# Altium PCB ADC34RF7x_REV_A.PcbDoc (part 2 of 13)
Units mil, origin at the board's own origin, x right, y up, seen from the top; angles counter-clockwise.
Board outline 6250 x 2716.54 mil, 18 copper layers (Top Layer, L2 GND, L3 PWR, L4 GND, L5 PWR/SIG, L6 GND, L7 SIGNAL, L8 GND, L9 GND, L10 SIGNAL, L11 GND, L12 SIGNAL, L13 GND, L14 PWR, L15 GND, L16 PWR/SIG, L16 GND, Bottom Layer), stack 95.314 mil thick; 668 components, 786 nets, 3150 pads, 2020 vias.
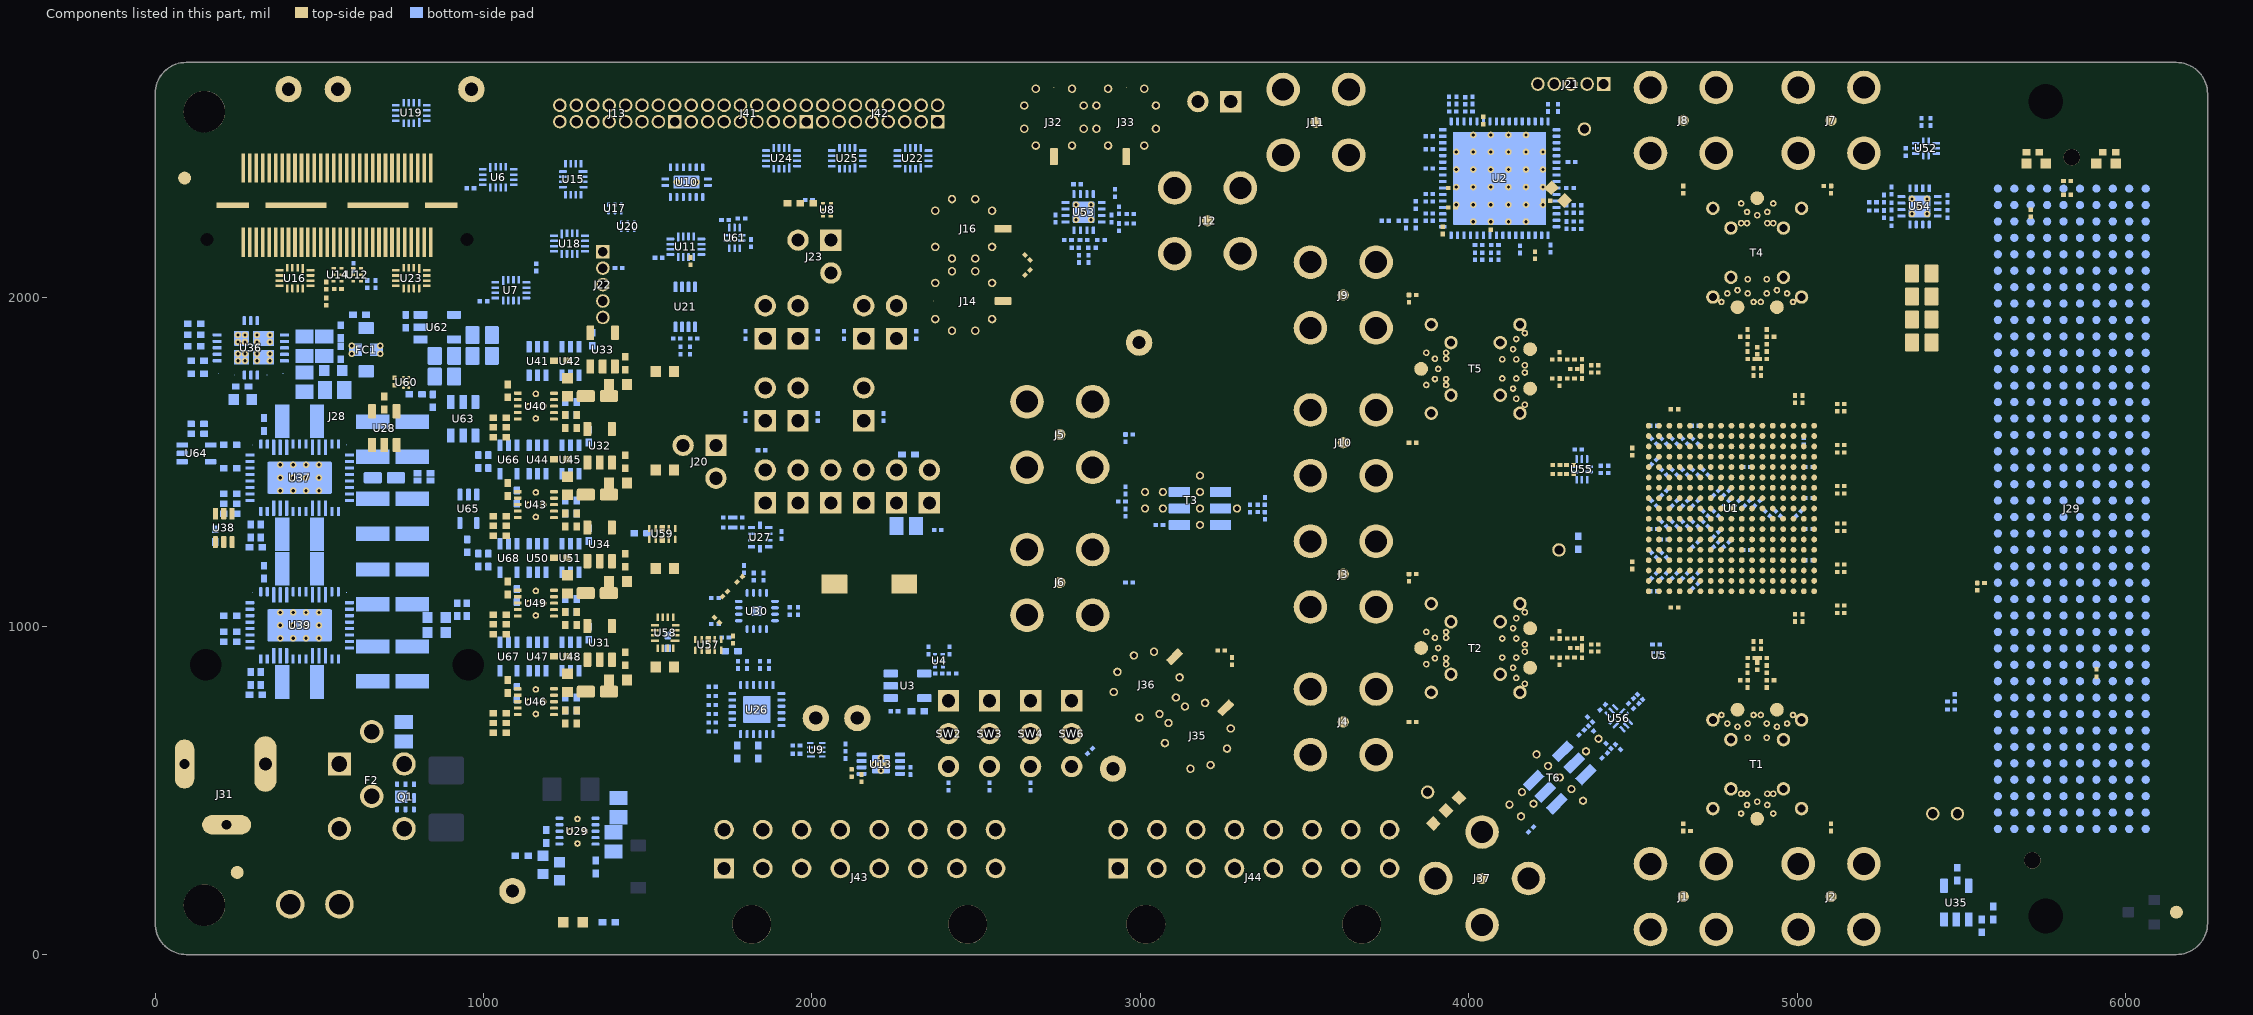
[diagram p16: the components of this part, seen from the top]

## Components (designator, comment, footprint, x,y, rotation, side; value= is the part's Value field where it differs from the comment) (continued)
FB5 "BLE18PS080SN1D" 0603L 857.08,1025.51 r0 bottom value=-
FB6 "BLE18PS080SN1D" 0603L 1409.53,1735.95 r0 top value=-
FB7 "BLE18PS080SN1D" 0603L 1409.53,1435.95 r0 top value=-
FB8 "BLE18PS080SN1D" 0603L 1409.53,835.95 r0 top value=-
FB9 "BLE18PS080SN1D" 0603L 1409.53,1135.95 r0 top value=-
FB10 "BLE18PS080SN1D" 0603L 1552.52,875.95 r180 top value=-
FB11 "BLE18PS080SN1D" 0603L 1552.52,1175.95 r180 top value=-
FC1 "NFM31PC276B0J3L" NFM31PC 642.24,1841.65 r90 bottom value=27uF
FID1 "Fiducial" Fiducial10-20 6155,128.83 r90 top
FID2 "Fiducial" Fiducial10-20 89.84,2364.25 r90 top
FID3 "Fiducial" Fiducial10-20 250,250 r90 top
H2 "2069-440-SS" FP-2116-440-AL_STANDOFF_HEX_1-4-MFG 150,150 r0 top
H4 "2069-440-SS" FP-2116-440-AL_STANDOFF_HEX_1-4-MFG 150,2566.54 r180 bottom
J1 "132134-15" FP-132134-15_CONN_SMA_JACK-MFG 4653.52,176.33 r270 top
J2 "132134-15" FP-132134-15_CONN_SMA_JACK-MFG 5103.52,176.33 r90 top
J3 "132134-15" FP-132134-15_CONN_SMA_JACK-MFG 3618.06,1158.29 r270 top
J4 "132134-15" FP-132134-15_CONN_SMA_JACK-MFG 3618.06,708.29 r270 top
J5 "132134-15" FP-132134-15_CONN_SMA_JACK-MFG 2755,1583.28 r0 top
J6 "132134-15" FP-132134-15_CONN_SMA_JACK-MFG 2755,1133.28 r0 top
J7 "132134-15" FP-132134-15_CONN_SMA_JACK-MFG 5103.54,2540.21 r270 top
J8 "132134-15" FP-132134-15_CONN_SMA_JACK-MFG 4653.54,2540.21 r270 top
J9 "132134-15" FP-132134-15_CONN_SMA_JACK-MFG 3618.06,2008.27 r0 top
J10 "132134-15" FP-132134-15_CONN_SMA_JACK-MFG 3618.06,1558.27 r0 top
J11 "132134-15" FP-132134-15_CONN_SMA_JACK-MFG 3534.82,2534.21 r180 top
J12 "132134-15" FP-132134-15_CONN_SMA_JACK-MFG 3204.82,2234.21 r0 top
J13 "GRPB082VWVN-RC" HDR_8x2_TH_VT_50mil 1407.61,2561.06 r180 top
J14 "0853050232" Molex_0853050232 2582.11,1989.88 r270 top
J15 "TSW-102-14-L-S" PBC02SAAN 2157.76,1425.36 r180 top
J16 "0853050232" Molex_0853050232 2582.11,2209.88 r270 top
J17 "TSW-102-14-L-S" PBC02SAAN 2057.76,1425.36 r180 top
J18 "TSW-102-14-L-S" PBC02SAAN 1957.76,1425.36 r180 top
J19 "GRPB021VWVN-RC" PBC02SAAN 2257.76,1425.36 r180 top
J20 "L-Header" l-header 1707.76,1550.36 r0 top
J21 "GRPB051VWVN-RC" HDR_5x1_TH_VT_50mil 4335.66,2650.7 r180 top
J22 "GRPB051VWVN-RC" HDR_5x1_TH_VT_50mil 1363.54,2065.01 r270 top
J23 "L-Header" l-header 2057.76,2175.36 r0 top
J24 "GRPB021VWVN-RC" PBC02SAAN 1857.76,1925.36 r180 top
J25 "GRPB021VWVN-RC" PBC02SAAN 1957.76,1925.36 r180 top
J26 "GRPB021VWVN-RC" PBC02SAAN 2157.76,1925.36 r180 top
J27 "GRPB021VWVN-RC" PBC02SAAN 2257.76,1925.36 r180 top
J28 "QSH-030-01-L-D-A" FTDI_Dongle_003 553.9,1657.2 r90 top locked
J29 "ASP-134488-01" SAMTEC_ASP-134488-01 5836.42,1358.27 r90 bottom locked
J30 "GRPB021VWVN-RC" PBC02SAAN 2157.76,1675.36 r180 top
J31 "RAPC722X" RAPC722X -223.11,580.14 r0 top
J32 "0853050232" Molex_0853050232 2737,2429.71 r180 top
J33 "0853050232" Molex_0853050232 2957,2429.71 r180 top
J34 "GRPB021VWVN-RC" PBC02SAAN 1957.76,1675.36 r180 top
J35 "0853050232" Molex_0853050232 3259.91,750.94 r315 top
J36 "0853050232" Molex_0853050232 3104.35,906.51 r315 top
J37 "132134-15" FP-132134-15_CONN_SMA_JACK-MFG 4040.75,231.61 r135 top
J38 "GRPB021VWVN-RC" PBC02SAAN 1857.76,1425.36 r180 top
J39 "GRPB021VWVN-RC" PBC02SAAN 3225.43,2597.26 r270 top
J40 "GRPB021VWVN-RC" PBC02SAAN 1857.76,1675.36 r180 top
J41 "GRPB082VWVN-RC" HDR_8x2_TH_VT_50mil 1807.62,2561.06 r180 top
J42 "GRPB082VWVN-RC" HDR_8x2_TH_VT_50mil 2207.63,2561.06 r180 top
J43 "43045-1602" 43045-1602 1732.47,262 r180 bottom locked
J44 "43045-1602" 43045-1602 2932.47,262 r180 bottom locked
J45 "GRPB021VWVN-RC" PBC02SAAN 2357.76,1425.36 r180 top
LBL1 "THT-14-423-10" Label_650x200 5750,1300 r90 top
LOGO1 "ESD Overlay" ESD_Overlay_Small 1115.68,495.66 r0 top (schematic designator Logo1)
Logo2 "CAUTION HOT SURFACE" IEC_HotSurface_Small 3144.84,1475.95 r0 top (schematic designator LOGO2)
Logo3 "Texas Instruments" TI_Stacked_Overlay_Medium 6014.98,1545.21 r90 top
Logo4 "CE Mark" CE_Mark_5mm 4829.79,513.59 r180 bottom (schematic designator LOGO4)
Logo5 "FCC disclaimer" FCC_disclaimer 2690,2485 r180 bottom
Logo6 "WEEE" WEEE_Minimum 5185.1,632.27 r180 bottom
Logo12 "FDL Logo" FDL_Small 874.66,1893.42 r0 top
MP1 "ATS-54170R-C1-R0" "DAC39 - ATS-54170R-C1-R0_BGA_HEATSINK_17p0x17p0mm" 4800,1358.27 r90 top
MP2 "Fan" "DAC39R - F17HA-05HC_FAN_17p0x17p0mm" 5135,1358.27 r0 top
NT1 "Net-Tie" Net-Tie_6x8mil 4998.88,1379.86 r135 top net-tie
NT2 "Net-Tie" Net-Tie_6x8mil 5030.37,1537.34 r135 top net-tie
NT3 "Net-Tie" Net-Tie_6x8mil 4569.63,1348.37 r45 top net-tie
NT4 "Net-Tie" Net-Tie_6x8mil 4569.63,1285.38 r45 top net-tie
NT5 "Net-Tie" Net-Tie_6x8mil 4935.88,1348.37 r135 top net-tie
NT6 "Net-Tie" Net-Tie_50milWide_30milLong#1 820.35,1357.6 r270 top net-tie
NT7 "Net-Tie" Net-Tie_50milWide_30milLong#2 886.59,1450.36 r0 top net-tie
NT8 "Net-Tie" Net-Tie_6x8mil 4872.89,1368.17 r225 top net-tie
PP1 "Probe Point" ProbePoint_TH_40mil 5488.35,428.77 r90 top
PP2 "Probe Point" ProbePoint_TH_40mil 5413.35,428.77 r90 top
PP3 "Probe Point" ProbePoint_TH_40mil 3874.91,494.48 r315 top
PP4 "Probe Point" ProbePoint_TH_40mil 4352.42,2513.5 r90 top
PP5 "Probe Point" ProbePoint_TH_40mil 4274.9,1231.88 r90 top
Q1 "CSD15571Q2" DQK0006C 762.52,480.3 r270 bottom
R1 "RC0201FR-078R66L" 0201#1 4849.4,869.23 r90 top value="8.66 Ω"
R2 "RC0201FR-078R66L" 0201#1 4867.51,942.28 r90 top value="8.66 Ω"
R3 "ERJ-1GNF1400C" 0201#1 4860.42,903.25 r180 top value="140 Ω"
R4 "ERJ-1GNF1001C" 0201#1 4626.77,1056.3 r180 top value="1 kΩ"
R5 "ERJ-1GNF1400C" 0201#1 4896.62,903.25 r180 top value="140 Ω"
R6 "RC0201FR-078R66L" 0201#1 4907.64,869.23 r90 top value="8.66 Ω"
R7 "RC0201FR-078R66L" 0201#1 4889.56,942.15 r90 top value="8.66 Ω"
R8 "RC0201FR-078R66L" 0201#1 4310.96,962.41 r0 top value="8.66 Ω"
R9 "RC0201FR-078R66L" 0201#1 4383.88,944.33 r0 top value="8.66 Ω"
R10 "ERJ-1GNF1400C" 0201#1 4344.98,951.39 r90 top value="140 Ω"
R11 "ERJ-1GNF1001C" 0201#1 4498.03,1185.02 r90 top value="1 kΩ"
R12 "ERJ-1GNF1400C" 0201#1 4344.98,915.19 r90 top value="140 Ω"
R13 "RC0201FR-078R66L" 0201#1 4310.96,904.17 r0 top value="8.66 Ω"
R14 "RC0201FR-078R66L" 0201#1 4383.88,922.25 r0 top value="8.66 Ω"
R15 "ERJ-1GN0R00C" 0201#1 2955,1413.45 r270 bottom value="0 Ω"
R16 "ERJ-1GN0R00C" 0201#1 2955,1345.4 r270 bottom value="0 Ω"
R17 "RC0201FS-7D100RL" 0201L 3334.24,1358.28 r270 bottom value=100
R18 "ERJ-1GNF16R0C" 0201#1 2943.98,1379.43 r0 bottom value="16 Ω"
R19 "RC0201FR-078R66L" 0201#1 4907.67,1847.31 r270 top value="8.66 Ω"
R20 "RC0201FR-078R66L" 0201#1 4889.56,1774.26 r270 top value="8.66 Ω"
R21 "ERJ-1GNF1400C" 0201#1 4896.64,1813.28 r0 top value="140 Ω"
R22 "ERJ-1GNF1001C" 0201#1 4626.77,1660.24 r0 top value="1 kΩ"
R23 "ERJ-1GNF1400C" 0201#1 4860.45,1813.28 r0 top value="140 Ω"
R24 "RC0201FR-078R66L" 0201#1 4849.42,1847.31 r270 top value="8.66 Ω"
R25 "RC0201FR-078R66L" 0201#1 4867.51,1774.39 r270 top value="8.66 Ω"
R26 "RC0201FR-078R66L" 0201#1 4310.96,1812.39 r0 top value="8.66 Ω"
R27 "RC0201FR-078R66L" 0201#1 4384.01,1794.28 r0 top value="8.66 Ω"
R28 "ERJ-1GNF1400C" 0201#1 4344.98,1801.37 r90 top value="140 Ω"
R29 "ERJ-1GNF1001C" 0201#1 4498.03,1531.5 r90 top value="1 kΩ"
R30 "ERJ-1GNF1400C" 0201#1 4344.98,1765.17 r90 top value="140 Ω"
R31 "RC0201FR-078R66L" 0201#1 4310.96,1754.15 r0 top value="8.66 Ω"
R32 "RC0201FR-078R66L" 0201#1 4383.88,1772.23 r0 top value="8.66 Ω"
R33 "ERJ-1GN0R00C" 0201#1 3797.89,2234.21 r180 bottom value="0 Ω"
R34 "ERJ-1GNF5600C" 0201#1 4297.42,2220.86 r270 bottom value="560 Ω"
R35 "ERJ-1GNF5600C" 0201#1 4297.42,2270.23 r270 bottom value="560 Ω"
R36 "ERJ-1GNF5600C" 0201#1 4079.5,2160.43 r180 bottom value="560 Ω"
R37 "ERJ-1GNF5600C" 0201#1 4030.13,2160.43 r180 bottom value="560 Ω"
R38 "ERJ-1GNF5600C" 0201#1 4000.76,2566.89 r0 bottom value="560 Ω"
R39 "ERJ-1GNF5600C" 0201#1 3951.39,2566.89 r0 bottom value="560 Ω"
R40 "ERJ-1GNF1002C" 0201#1 4313.44,2412.87 r0 bottom value="10 kΩ"
R41 "ERJ-1GN0R00C" 0201#1 1740.67,1300.41 r180 bottom value="0 Ω"
R42 "ERJ-1GN0R00C" 0201#1 1792.72,1173.37 r90 bottom value="0 Ω"
R43 "ERJ-1GN0R00C" 0201#1 2656.36,2077.09 r225 top value="0 Ω"
R44 "ERJ-1GN0R00C" 0201#1 2656.36,2122.68 r135 top value="0 Ω"
R45 "ERJ-1GN0R00C" 0201#1 2386.19,855.43 r0 bottom value="0 Ω"
R46 "ERJ-1GNF1002C" 0201#1 2418.79,925.83 r270 bottom value="10 kΩ"
R47 "ERJ-1GNF1002C" 0201#1 2355.16,925.83 r90 bottom value="10 kΩ"
R48 "ERJ-1GNF1002C" 0201#1 2428.24,855.43 r180 bottom value="10 kΩ"
R49 "ERJ-1GN0R00C" 0201#1 2251.02,740.77 r0 bottom value="0 Ω"
R50 "ERJ-1GNF1002C" 0201#1 1630.62,2111.5 r90 top value="10 kΩ"
R51 "ERJ-HP6F1000V" 0805L#1 2287.28,1305.36 r0 bottom value="100 Ω"
R52 "ERJ-1GNF4701C" 0201#2 1990.98,2297.79 r180 bottom value="4.7 kΩ"
R53 "ERJ-1GNF1000C" 0201#1 4202.45,2129.41 r270 top value="100 Ω"
R54 "ERJ-1GN0R00C" 0201#1 4331.44,2232.19 r0 bottom value="0 Ω"
R55 "ERJ-1GN0R00C" 0201#1 4331.44,2209.54 r0 bottom value="0 Ω"
R56 "ERJ-1GNF4701C" 0201#2 4271.82,2577.91 r90 bottom value="4.7 kΩ"
R57 "ERJ-1GNF1002C" 0201#1 959.87,2333.5 r0 bottom value="10 kΩ"
R58 "ERJ-1GN0R00C" 0201#1 4331.44,2281.56 r0 bottom value="0 Ω"
R59 "ERJ-1GNF1000C" 0201#1 1411.34,2090.01 r0 bottom value="100 Ω"
R60 "ERJ-2GE0R00X" 0402L#1 1945.08,2287.75 r180 top value="0 Ω"
R61 "ERJ-1GN0R00C" 0201#1 4331.44,2258.91 r0 bottom value="0 Ω"
R62 "ERJ-1GN0R00C" 0201#1 4090.83,2126.41 r270 bottom value="0 Ω"
R63 "ERJ-1GN0R00C" 0201#1 4068.18,2126.41 r270 bottom value="0 Ω"
R64 "ERJ-2GE0R00X" 0402L#1 1984.45,2287.75 r180 top value="0 Ω"
R65 "ERJ-1GNF1002C" 0201#1 1000.09,1989.25 r0 bottom value="10 kΩ"
R66 "ERJ-1GNF3741C" 0201#1 1932.4,1046.01 r270 bottom value="3.74 kΩ"
R67 "ERJ-1GNF3741C" 0201#1 1957.4,1046.01 r270 bottom value="3.74 kΩ"
R68 "ERJ-1GN0R00C" 0201#1 670.87,2041.49 r90 bottom value="0 Ω"
R69 "ERJ-1GN0R00C" 0201#1 1952.52,636.2 r0 bottom value="0 Ω"
R70 "ERJ-1GN0R00C" 0201#1 604.43,2094.38 r270 bottom value="0 Ω"
R71 "ERJ-1GNF1002C" 0201#1 2317.76,1886.39 r90 bottom value="10 kΩ"
R72 "ERJ-1GNF1002C" 0201#1 2097.76,1886.39 r90 bottom value="10 kΩ"
R73 "ERJ-1GNF1002C" 0201#1 1797.76,1886.39 r90 bottom value="10 kΩ"
R74 "ERJ-1GNF1002C" 0201#1 2017.76,1886.39 r90 bottom value="10 kΩ"
R75 "ERJ-1GNF1002C" 0201#1 1533.11,2121.54 r0 bottom value="10 kΩ"
R76 "ERJ-1GNF49R9C" 0201#1 3838.91,2282.24 r90 bottom value="49.9 Ω"
R77 "ERJ-1GNF49R9C" 0201#1 3838.91,2223.18 r90 bottom value="49.9 Ω"
R78 "ERJ-1GNF1000C" 0201#1 556.34,2026.04 r180 top value="100 Ω"
R79 "ERJ-1GNF1002C" 0201#1 2847.21,619.26 r225 bottom value="10 kΩ"
R80 "ERJ-1GN0R00C" 0201#1 3989.44,2599.91 r90 bottom value="0 Ω"
R81 "ERJ-1GN0R00C" 0201#1 4012.09,2600.91 r90 bottom value="0 Ω"
R82 "ERJ-1GN0R00C" 0201#1 521.32,2037.06 r270 top value="0 Ω"
R83 "ERJ-H2GJ392X" 0402L#1 5950.79,2443.52 r0 top value="3.9 kΩ"
R84 "ERJ-1GN0R00C" 0201#1 5911.42,857.27 r90 top value="0 Ω"
R85 "ERJ-1GNF2200C" 0201#1 5822.44,2313.53 r180 top value="220 Ω"
R86 "ERJ-1GNF2200C" 0201#1 5711.42,2257.27 r90 top value="220 Ω"
R87 "ERJ-PA2F1001X" 0402L#1 5718.05,2443.51 r180 top value="1 kΩ"
R88 "ERJ-1GNF1002C" 0201#1 2217.76,1636.39 r90 bottom value="10 kΩ"
R89 "ERJ-1GNF2201C" 0201#1 2666.03,511.53 r270 bottom value="2.2 kΩ"
R90 "ERJ-1GNF2201C" 0201#1 2416.03,511.53 r270 bottom value="2.2 kΩ"
R91 "ERJ-1GNF2201C" 0201#1 2541.03,511.53 r270 bottom value="2.2 kΩ"
R92 "ERJ-1GNF2201C" 0201#1 1696.45,678.8 r180 bottom value="2.2 kΩ"
R93 "ERJ-1GNF2201C" 0201#1 1696.45,706.48 r180 bottom value="2.2 kΩ"
R94 "ERJ-1GNF2201C" 0201#1 1696.45,732.17 r180 bottom value="2.2 kΩ"
R95 "ERJ-1GNF2201C" 0201#1 1696.45,759.85 r180 bottom value="2.2 kΩ"
R96 "ERJ-1GNF2201C" 0201#1 1696.45,787.54 r180 bottom value="2.2 kΩ"
R97 "ERJ-1GNF2201C" 0201#1 1696.45,815.22 r180 bottom value="2.2 kΩ"
R98 "ERJ-1GNF2201C" 0201#1 1775.07,881.83 r90 bottom value="2.2 kΩ"
R99 "ERJ-1GNF2201C" 0201#1 1802.75,881.83 r90 bottom value="2.2 kΩ"
R100 "ERJ-1GNF2201C" 0201#1 1842.12,881.83 r90 bottom value="2.2 kΩ"
R101 "ERJ-1GNF2201C" 0201#1 1869.81,881.83 r90 bottom value="2.2 kΩ"
R102 "ERJ-PA2F1002X" 0402L#1 1773.07,616.52 r270 bottom value="10 kΩ"
R103 "CSS0603FT2L00" CCS0603FLxLxx 698.1,1451.77 r0 bottom value="2 mΩ"
R104 "CSS0603FT10L0" CCS0603FLxLxx 1346.93,800.51 r0 top value="10 mΩ"
R105 "CSS0603FT10L0" CCS0603FLxLxx 1346.93,1400.51 r0 top value="10 mΩ"
R106 "CSS0603FT10L0" CCS0603FLxLxx 1346.93,1700.51 r0 top value="10 mΩ"
R107 "CSS0603FT10L0" CCS0603FLxLxx 1346.54,1100.51 r0 top value="10 mΩ"
R108 "ERJ-2GEJ104X" 0402L#1 1191.1,359.42 r90 bottom value="100 kΩ"
R109 "ERJ-2RKF7682X" 0402L#1 1341.26,266.36 r90 bottom value="76.8 kΩ"
R110 "ERJ-2RKF1742X" 0402L#1 1381.74,98.59 r180 bottom value="17.4 kΩ"
R111 "ERJ-2RKF1622X" 0402L#1 1116.46,300.1 r0 bottom value="16.2 kΩ"
R112 "ERJ-PA2F1002X" 0402L#1 129.41,1767.95 r180 bottom value="10 kΩ"
R113 "ERJ-PA2F4701X" 0402L#1 119.41,1886.69 r0 bottom value="4.7 kΩ"
R114 "ERA-2APB1542X" 0402L#1 565.28,1832.36 r270 bottom value="15.4 kΩ"
R115 "ERJ-PA2F4701X" 0402L#1 119.41,1920.69 r180 bottom value="4.7 kΩ"
R116 "ERJ-2RKF8062X" 0402L#1 119.41,1852.01 r0 bottom value="80.6 kΩ"
R117 "ERA-2APB4871X" 0402L#1 565.28,1896.73 r270 bottom value="4.87 kΩ"
R118 "ERJ-PA2F1002X" 0402L#1 331.53,1613.82 r270 bottom value="10 kΩ"
R119 "ERA-2AEB5231X" 0402L#1 228.69,1402.56 r180 bottom value="5.23 kΩ"
R120 "ERA-2AEB113X" 0402L#1 228.69,1372.56 r0 bottom value="11 kΩ"
R121 "ERA-2AEB113X" 0402L#1 228.69,1342.56 r0 bottom value="11 kΩ"
R122 "ERA-2APB1072X" 0402L#1 321.84,1289.72 r90 bottom value="10.7 kΩ"
R123 "ERJ-PA2F1002X" 0402L#1 291.84,1289.72 r90 bottom value="10 kΩ"
R124 "ERJ-2RKF1742X" 0402L#1 306.84,1240.04 r180 bottom value="17.4 kΩ"
R125 "ERJ-PA2F1002X" 0402L#1 331.53,1164.33 r270 bottom value="10 kΩ"
R126 "ERA-2APB363X" 0402L#1 228.69,983.07 r180 bottom value="36 kΩ"
R127 "ERJ-PA2F1002X" 0402L#1 228.69,953.07 r0 bottom value="10 kΩ"
R128 "ERA-2APB1072X" 0402L#1 321.84,840.23 r90 bottom value="10.7 kΩ"
R129 "ERJ-PA2F1002X" 0402L#1 291.84,840.23 r90 bottom value="10 kΩ"
R130 "ERJ-2RKF5362X" 0402L#1 306.84,790.55 r180 bottom value="53.6 kΩ"
R131 "ERJ-PA2F1002X" 0402L#1 1049.69,1635 r180 top value="10 kΩ"
R132 "ERA-2AEB8871X" 0402L#1 1249.61,1662.72 r270 bottom value="8.87 kΩ"
R133 "ERJ-2RKF5492X" 0402L#1 1049.69,1605 r180 top value="54.9 kΩ"
R134 "ERA-2ARB2322X" 0402L#1 1284.61,1623.35 r90 top value="23.2 kΩ"
R135 "ERJ-2RKF1242X" 0402L#1 1049.68,1575 r0 top value="12.4 kΩ"
R136 "ERA-2AEB104X" 0402L#1 1284.61,1662.72 r270 bottom value="100 kΩ"
R137 "ERJ-PA2F1002X" 0402L#1 1049.69,1335 r180 top value="10 kΩ"
R138 "ERA-2AEB8871X" 0402L#1 1249.61,1362.72 r270 bottom value="8.87 kΩ"
R139 "ERJ-2RKF5492X" 0402L#1 1049.69,1305 r180 top value="54.9 kΩ"
R140 "ERA-2ARB2322X" 0402L#1 1284.61,1323.35 r90 top value="23.2 kΩ"
R141 "ERJ-2RKF1242X" 0402L#1 1049.68,1275 r0 top value="12.4 kΩ"
R142 "ERA-2AEB104X" 0402L#1 1284.61,1362.72 r270 bottom value="100 kΩ"
R143 "ERJ-PA2F1002X" 0402L#1 1049.69,735 r180 top value="10 kΩ"
R144 "ERA-2ARB1652X" 0402L#1 1249.61,762.72 r90 bottom value="16.5 kΩ"
R145 "ERA-2AEB8872X" 0402L#1 1049.69,705 r180 top value="88.7 kΩ"
R146 "ERA-2ARB3742X" 0402L#1 1284.61,723.35 r90 top value="37.4 kΩ"
R147 "ERJ-2RKF1242X" 0402L#1 1049.68,675 r0 top value="12.4 kΩ"
R148 "ERA-2AEB104X" 0402L#1 1284.61,762.72 r270 bottom value="100 kΩ"
R149 "ERJ-PA2F1002X" 0402L#1 1049.69,1035 r180 top value="10 kΩ"
R150 "ERA-2ARB1652X" 0402L#1 1249.61,1062.72 r90 bottom value="16.5 kΩ"
R151 "ERA-2AEB8872X" 0402L#1 1049.69,1005 r180 top value="88.7 kΩ"
R152 "ERA-2ARB3742X" 0402L#1 1284.61,1023.35 r90 top value="37.4 kΩ"
R153 "ERJ-2RKF1242X" 0402L#1 1049.68,975 r0 top value="12.4 kΩ"
R154 "ERA-2AEB104X" 0402L#1 1284.61,1062.72 r270 bottom value="100 kΩ"
R155 "ERJ-1GNF1000C" 0201#1 2807.62,2345.55 r0 bottom value="100 Ω"
R156 "ERJ-1GNF1000C" 0201#1 5457.96,2301.4 r270 bottom value="100 Ω"
R157 "ERJ-1GNF49R9C" 0201#1 2801.77,2152.32 r0 bottom value="49.9 Ω"
R158 "ERJ-1GNF49R9C" 0201#1 2852.86,2152.32 r180 bottom value="49.9 Ω"
R159 "ERJ-1GNF49R9C" 0201#1 5264.73,2301.58 r270 bottom value="49.9 Ω"
R160 "ERJ-1GNF49R9C" 0201#1 5264.73,2254.48 r90 bottom value="49.9 Ω"
R161 "ERJ-1GNF1000C" 0201#1 5457.96,2255.02 r270 bottom value="100 Ω"
R162 "ERJ-1GNF1002C" 0201#1 2017.76,1636.39 r90 bottom value="10 kΩ"
R163 "ERJ-1GNF1002C" 0201#1 1846.73,1535.36 r0 bottom value="10 kΩ"
R164 "ERJ-1GN0R00C" 0201#1 3279.03,893.39 r270 top value="0 Ω"
R165 "ERJ-1GNF1002C" 0201#1 1797.76,1636.39 r90 bottom value="10 kΩ"
R166 "ERJ-1GN0R00C" 0201#1 3940.07,2600.91 r90 bottom value="0 Ω"
R167 "ERJ-1GN0R00C" 0201#1 1704.92,1085.52 r180 bottom value="0 Ω"
R168 "ERJ-1GN0R00C" 0201#1 1704.92,1006.45 r180 bottom value="0 Ω"
R169 "ERJ-1GN0R00C" 0201#1 1736.68,965.89 r180 bottom value="0 Ω"
R170 "ERJ-1GN0R00C" 0201#1 1776.89,1300.44 r0 bottom value="0 Ω"
R171 "ERJ-1GN0R00C" 0201#1 1780.14,1142.66 r225 top value="0 Ω"
R172 "ERJ-1GN0R00C" 0201#1 1735.07,1097.57 r45 top value="0 Ω"
R173 "ERJ-1GN0R00C" 0201#1 1710.98,1018.51 r135 top value="0 Ω"
R174 "ERJ-1GN0R00C" 0201#1 1759.2,958.87 r270 top value="0 Ω"
R175 "ERJ-1GNF1000C" 0201#1 2827.31,2175.32 r0 bottom value="100 Ω"
R176 "ERJ-1GNF1000C" 0201#1 5287.73,2278.03 r270 bottom value="100 Ω"
R177 "ERJ-1GN0R00C" 0201#1 3246.55,925.88 r180 top value="0 Ω"
R178 "ERJ-1GNF1000C" 0201#1 2742.2,2240.74 r90 bottom value="100 Ω"
R179 "ERJ-PA2F1002X" 0402L#1 5597.52,126.69 r270 bottom value="10 kΩ"
R180 "ERJ-1GNF1000C" 0201#1 4522.09,784.37 r135 bottom value="100 Ω"
R181 "ERJ-1GN0R00C" 0201#1 3962.72,2600.91 r90 bottom value="0 Ω"
R182 "ERJ-1GN0R00C" 0201#2 5480.09,781.76 r90 bottom value="0 Ω"
R183 "ERJ-1GN0R00C" 0201#2 5469.07,770.74 r180 bottom value="0 Ω"
R184 "ERJ-1GN0R00C" 0201#2 5469.07,745.74 r180 bottom value="0 Ω"
R185 "ERJ-1GN0R00C" 0201#1 521.32,1988.02 r90 top value="0 Ω"
R186 "ERJ-1GN0R00C" 0201#1 1952.52,611.2 r0 bottom value="0 Ω"
R187 "ERJ-1GNF1000C" 0201#1 1160.6,2092.52 r90 bottom value="100 Ω"
R188 "ERJ-1GNF1000C" 0201#1 2912.43,2240.74 r270 bottom value="100 Ω"
R189 "ERJ-1GNF1002C" 0201#1 4308.89,1490.75 r0 top value="10 kΩ"
R190 "ERJ-1GNF1002C" 0201#1 4308.89,1463.74 r0 top value="10 kΩ"
R191 "ERJ-1GNF1002C" 0201#1 4369.72,715.91 r135 bottom value="10 kΩ"
R192 "ERJ-1GNF1002C" 0201#1 4454.28,632.31 r315 bottom value="10 kΩ"
R193 "ERJ-1GNF1002C" 0201#1 4266.84,1490.75 r0 top value="10 kΩ"
R194 "ERJ-1GNF1002C" 0201#1 4266.84,1463.74 r0 top value="10 kΩ"
R195 "ERJ-1GNF1002C" 0201#1 4372.86,687.69 r135 bottom value="10 kΩ"
R196 "ERJ-1GNF1002C" 0201#1 4425.65,634.9 r315 bottom value="10 kΩ"
R197 "ERJ-1GN0R00C" 0201#1 1740.67,1330.41 r180 bottom value="0 Ω"
R198 "ERJ-1GN0R00C" 0201#1 1776.89,1330.44 r0 bottom value="0 Ω"
R199 "ERJ-1GNF2200C" 0201#1 5822.44,2355.76 r0 top value="220 Ω"
R200 "ERJ-1GN0R00C" 0201#2 5559.73,1131.13 r0 top value="0 Ω"
R201 "ERJ-1GN0R00C" 0201#2 5548.71,1120.11 r90 top value="0 Ω"
R202 "ERJ-U030R00V" 0603L 3950.6,457.77 r225 top value="0 Ω"
R203 "ERJ-U030R00V" 0603L 3911.62,418.8 r225 top value="0 Ω"
R204 "ERJ-1GN0R00C" 0201#1 4413.54,1488.55 r0 bottom value="0 Ω"
R205 "ERJ-1GN0R00C" 0201#1 4413.54,1465.95 r0 bottom value="0 Ω"
R206 "ERJ-2GE0R00X" 0402L#2 228.69,1551.77 r0 bottom value="0 Ω"
R207 "ERJ-1GNF1000C" 0201#1 645.86,2041.5 r90 bottom value="100 Ω"
R208 "ERJ-1GNF49R9C" 0201#1 2935.43,2266.29 r270 bottom value="49.9 Ω"
R209 "ERJ-1GNF49R9C" 0201#1 2935.43,2215.2 r90 bottom value="49.9 Ω"
R210 "ERJ-1GNF1002C" 0201#1 2922.96,2318.81 r90 bottom value="10 kΩ"
R211 "ERJ-1GNF1002C" 0201#2 2102.45,607.95 r90 bottom value="10 kΩ"
R212 "ERJ-1GNF1002C" 0201#2 2151.24,537.02 r90 top value="10 kΩ"
R213 "ERJ-1GNF1002C" 0201#2 2121.24,552.66 r270 top value="10 kΩ"
R214 "ERJ-1GNF1002C" 0201#2 2102.45,629.99 r90 bottom value="10 kΩ"
R215 "ERJ-1GNF1002C" 0201#2 2383.25,1292.17 r0 bottom value="10 kΩ"
R216 "ERJ-1GNF1002C" 0201#2 1735.69,2236.55 r0 bottom value="10 kΩ"
R217 "ERJ-1GN0R00C" 0201#2 1640.21,1875.36 r0 bottom value="0 Ω"
R218 "ERJ-1GN0R00C" 0201#2 1588.47,1875.36 r180 bottom value="0 Ω"
R219 "ERJ-1GN0R00C" 0201#2 1814.87,2166.24 r270 bottom value="0 Ω"
R220 "ERJ-6GEY0R00V" 0805L#2 5379.53,2073.77 r180 top value="0 Ω"
R221 "ERJ-6GEY0R00V" 0805L#2 5379.53,2003.77 r180 top value="0 Ω"
R222 "ERJ-6GEY0R00V" 0805L#2 5379.53,1933.77 r180 top value="0 Ω"
R223 "ERJ-6GEY0R00V" 0805L#2 5379.53,1863.77 r180 top value="0 Ω"
R224 "ERJ-2GEJ104X" 0402L#2 793.29,1705.75 r180 bottom value="100 kΩ"
R225 "ERJ-PA2F4701X" 0402L#2 763.07,1928.01 r90 bottom value="4.7 kΩ"
R226 "ERJ-2RKF1622X" 0402L#2 845.87,1685.98 r90 bottom value="16.2 kΩ"
R227 "ERJ-2GE0R00X" 0402L#2 129.41,1585.76 r0 bottom value="0 Ω"
R228 "ERJ-2GE0R00X" 0402L#2 129.41,1615.76 r0 bottom value="0 Ω"
R229 "ERJ-2GE0R00X" 0402L#2 950.16,1244.43 r270 bottom value="0 Ω"
R230 "ERJ-2GE0R00X" 0402L#2 1101.81,1393.21 r270 bottom value="0 Ω"
R231 "ERJ-2GE0R00X" 0402L#2 984.58,1501.13 r270 bottom value="0 Ω"
R232 "ERJ-2GE0R00X" 0402L#2 1014.58,1501.13 r270 bottom value="0 Ω"
R233 "ERJ-2GE0R00X" 0402L#2 1101.81,795.6 r270 bottom value="0 Ω"
R234 "ERJ-2GE0R00X" 0402L#2 1101.81,1093.21 r270 bottom value="0 Ω"
R235 "ERJ-2GE0R00X" 0402L#2 984.58,1201.13 r270 bottom value="0 Ω"
R236 "ERJ-2GE0R00X" 0402L#2 1014.58,1201.13 r270 bottom value="0 Ω"
R237 "ERJ-1GNF1002C" 0201#2 1629.18,1839.34 r270 bottom value="10 kΩ"
R238 "ERJ-1GNF1002C" 0201#2 1599.89,1839.34 r270 bottom value="10 kΩ"
SH-J19 "SPC02SYAN" SPC02SYAN 2258.34,1426.45 r90 top value=1x2
SH-J20 "SPC02SYAN" SPC02SYAN 1708.6,1500.78 r270 top value=1x2
SH-J24 "SPC02SYAN" SPC02SYAN 1856.66,1923.44 r90 top value=1x2
SH-J25 "SPC02SYAN" SPC02SYAN 1956.71,1922.03 r90 top value=1x2
SH-J26 "SPC02SYAN" SPC02SYAN 2159.19,1925.96 r90 top value=1x2
SH-J27 "SPC02SYAN" SPC02SYAN 2257.65,1925.68 r90 top value=1x2
SH-J30 "SPC02SYAN" SPC02SYAN 2158.31,1672.3 r90 top value=1x2
SH-J34 "SPC02SYAN" SPC02SYAN 1956.54,1672.45 r90 top value=1x2
SH-J38 "SPC02SYAN" SPC02SYAN 1857.07,1424.24 r90 top value=1x2
SH-J39 "SPC02SYAN" SPC02SYAN 3175.43,2547.25 r90 top value=1x2
SH-J40 "SPC02SYAN" SPC02SYAN 1803.55,1720.9 r180 top value=1x2
SH-J45 "SPC02SYAN" SPC02SYAN 2357.81,1426.18 r90 top value=1x2
SW1 "434123050816" 434123050816 2175,1128.15 r0 top
SW2 "450301014042" 450301014042 2416.03,672.55 r90 top
SW3 "450301014042" 450301014042 2541.03,672.55 r90 top
SW4 "450301014042" 450301014042 2666.03,672.55 r90 top
SW6 "450301014042" 450301014042 2791.03,672.55 r90 top
T1 "BAL-0006SMG" Marki_BAL-000xSMG 4878.52,579.38 r180 top
T2 "BAL-0006SMG" Marki_BAL-000xSMG 4021.11,933.29 r90 top
T3 "TCM2-63WX+" "DB1627 - Vias 1,2,5" 3181.64,1358.28 r270 bottom
T4 "BAL-0006SMG" Marki_BAL-000xSMG 4878.54,2137.16 r0 top
T5 "BAL-0006SMG" Marki_BAL-000xSMG 4021.11,1783.27 r90 top
T6 "TCM2-43X+" TCM2-43X+ 4277.38,538.95 r315 bottom
TP3 "5003" Keystone5003 406.26,2635 r90 bottom
TP4 "5001" Keystone5001 1087.97,193.51 r90 top
TP5 "5001" Keystone5001 963.07,2635 r90 top
TP6 "5002" Keystone5002 2138.29,719.94 r90 top
TP7 "5002" Keystone5002 2011.8,719.94 r90 top
TP8 "5002" Keystone5002 556.26,2635 r90 bottom
TP9 "5001" Keystone5001 2996.52,1863.27 r90 top
TP10 "5001" Keystone5001 2916.8,565.81 r90 top
TP11 "5010" Keystone5010 411.34,153.29 r0 top
TP12 "5125" Keystone5125 561.34,153.29 r0 top
U1 "ADC34RF72ANH" ANH0289A 4800,1358.27 r270 top locked
U2 "LMK04828BISQ/NOPB" NKD0064A 4094.19,2363.66 r180 bottom
U3 "TPS3840DL16DBV" DBV0005A 2291.18,818.17 r0 bottom
U4 "SN74AUP1G08DRY" DRY0006A 2387.07,895.12 r180 bottom
U5 "TMP117AIYBGR" YBG0006AJAP 4578.88,911.42 r270 bottom
U6 "SN74CBTLV3257RSV" RSV0016A 1044.74,2367.13 r270 bottom
U7 "SN74CBTLV3257RSVR" RSV0016A 1083.36,2022.87 r270 bottom
U8 "SN74LVC1G126DRYR" DRY0006A 2046.04,2268.06 r180 top
U9 "TXS0102DQER" DQE0008A 2013.14,623.29 r0 bottom
U10 "TMUX1309BQBR" BQB0016A-MFG 1618.35,2351.93 r270 bottom
U11 "SN74CBTLV3257RSVR" RSV0016A 1616.38,2155.16 r270 bottom
U12 "SN74LVC1G125DRYR" DRY0006A 615.14,2069.72 r0 top
U13 "24LC64FT-I/MNY" TDFN8 2210.3,579.53 r0 bottom
U14 "SN74LVC1G125DRYR" DRY0006A 555.45,2069.72 r0 top
U15 "SN74AVC4T774RSV" RSV0016A 1273.36,2360.63 r180 bottom
U16 "SN74AVC4T774RSV" RSV0016A 425.94,2059.88 r270 top
U17 "SN74LVC1G125DRYR" DRY0006A 1400.31,2271.91 r270 bottom
U18 "SN74AVC4T774RSV" RSV0016A 1262.14,2165 r270 bottom
U19 "SN74AVC4T774RSV" RSV0016A 780.28,2562.56 r90 bottom
U20 "SN74LVC1G125DRYR" DRY0006A 1439.68,2218.09 r90 bottom
U21 "SN74AVCH2T45" DCU0008A 1614.34,1972.13 r90 bottom
U22 "SN74AVC4T774RSV" RSV0016A 2307.63,2424.56 r90 bottom
U23 "SN74AVC4T774RSV" RSV0016A 780.28,2059.88 r270 top
U24 "SN74AVC4T774RSV" RSV0016A 1907.62,2424.56 r90 bottom
U25 "SN74AVC4T774RSV" RSV0016A 2107.62,2424.56 r90 bottom
U26 "TCA9548ARGER" RGE0024C 1832.28,746.01 r0 bottom
U27 "ADS1114IRUGR" RUG0010A 1842.14,1270.91 r0 bottom
U28 "INA180B1IDBVR" DBV0005A 697.9,1602.95 r90 top
U29 "TPS259261DRC" DRC0010J 1286.14,375.42 r0 bottom
U30 "ADS1119IRTER" RTE0016D 1832.28,1046.01 r90 bottom
U31 "INA180B1IDBVR" DBV0005A 1353.73,949 r90 top
U32 "INA180B1IDBVR" DBV0005A 1353.73,1549 r90 top
U33 "INA180B1IDBVR" DBV0005A 1362.73,1842 r90 top
U34 "INA180B1IDBVR" DBV0005A 1353.73,1249 r90 top
U35 "TPS70950DBV" DBV0005A 5485,158.18 r90 bottom
U36 "TPSM82913RDUR" RDU0028A 291.46,1847.32 r270 bottom
U37 "TPSM5D1806RDB" RDB0051A 439.95,1451.78 r270 bottom
U38 "TPL0401A-10DCK" DCK0006A 209.01,1299.25 r90 top
U39 "TPSM5D1806RDB" RDB0051A 439.95,1002.28 r270 bottom
U40 "TPS7A9601DSC" DRC0010J 1159.49,1669.8 r0 top
U41 "TPL0401A-10DCK" DCK0006A 1164.72,1807.17 r270 bottom
U42 "TPL0401B-10DCK" DCK0006A 1264.72,1807.17 r270 bottom
U43 "TPS7A9601DSC" DRC0010J 1159.49,1369.8 r0 top
U44 "TPL0401A-10DCK" DCK0006A 1164.72,1507.17 r270 bottom
U45 "TPL0401B-10DCK" DCK0006A 1264.72,1507.17 r270 bottom
U46 "TPS7A9601DSC" DRC0010J 1159.49,769.8 r0 top
U47 "TPL0401A-10DCK" DCK0006A 1164.72,907.17 r270 bottom
U48 "TPL0401B-10DCK" DCK0006A 1264.72,907.17 r270 bottom
U49 "TPS7A9601DSC" DRC0010J 1159.49,1069.8 r0 top
U50 "TPL0401A-10DCK" DCK0006A 1164.72,1207.17 r270 bottom
U51 "TPL0401B-10DCK" DCK0006A 1264.72,1207.17 r270 bottom
U52 "" NKG0010A 5392.53,2454.89 r270 bottom
U53 "LMK1D1204" RGT0016C 2827.31,2260.43 r180 bottom
U54 "LMK1D1204" RGT0016C 5372.85,2278.12 r90 bottom
U55 "" NKG0010A 4344.64,1477.25 r180 bottom
U56 "" NKG0010A 4457.27,719.5 r225 bottom
U57 "TMUX1104DGS" DQA0010A 1684.51,942.76 r90 top
U58 "TCAL9538RSVR" RSV0016A 1553.59,979.59 r180 top
U59 "TMUX1104DGS" DQA0010A 1544.55,1280.55 r270 top
U60 "TMP117AIYBGR" YBG0006AJAP 764.53,1741.98 r0 top
U61 "TMUX121NKGR" NKG0010A 1764.47,2182.08 r180 bottom
U62 "TPS70950DBV" DBV0005A 859.25,1910.3 r0 bottom
U63 "LM3880MFE-1AA" DBV0006A 937.99,1631.22 r270 bottom
U64 "SN74AUP1G08DCKT" DCK0005A 125.7,1526.18 r0 bottom
U65 "SN74AUP1G08DCKT" DCK0005A 953.9,1357.31 r270 bottom
U66 "SN74AUP1G08DCKT" DCK0005A 1076.22,1507.17 r270 bottom
U67 "SN74AUP1G08DCKT" DCK0005A 1076.22,907.17 r270 bottom
U68 "SN74AUP1G08DCKT" DCK0005A 1076.22,1207.17 r270 bottom
ZZ1 "This Assembly Note is for PCB labels only" AssemblyNoteLabel 151.23,3112.5 r0 top
ZZ2 "These assemblies are ESD sensitive, ESD precautions shall be observed." AssemblyNote 151.23,3262.11 r0 top
ZZ3 "These assemblies must be clean and free from flux and all contaminants. Use of no clean flux is not acceptable." AssemblyNote 151.23,3411.73 r0 top
ZZ4 "These assemblies must comply with workmanship standards IPC-A-610 Class 2, unless otherwise specified." AssemblyNote 151.23,3560.36 r0 top

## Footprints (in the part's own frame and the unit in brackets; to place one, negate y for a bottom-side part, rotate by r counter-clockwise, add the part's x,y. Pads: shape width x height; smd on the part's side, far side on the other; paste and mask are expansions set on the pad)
0201#1 [mm] "Data from Kemet datasheet CC101_COM dated 7/28/11"
  rect 0.36x0.32 smd mask+0.048: 1(-0.28,0) 2(0.28,0)
  body extent -0.31,-0.16 0.31,0.16, height 0.26
0201#2 [mm] "Data from Kemet datasheet CC101_COM dated 7/28/11"
  rrect20% 0.36x0.32 smd mask+0.051: 1(-0.28,0) 2(0.28,0)
  body extent -0.31,-0.16 0.31,0.16, height 0.26
0201_cap#1 [mm] "Data from Kemet datasheet CC101_COM dated 7/28/11"
  rect 0.36x0.32 smd mask+0.048: 1(-0.28,0) 2(0.28,0)
  body extent -0.31,-0.16 0.31,0.16, height 0.26
0201_cap#2 [mm] "Data from Kemet datasheet CC101_COM dated 7/28/11"
  rrect20% 0.36x0.32 smd mask+0.051: 1(-0.28,0) 2(0.28,0)
  body extent -0.31,-0.16 0.31,0.16, height 0.26
0201L [mm] "Data from Kemet datasheet CC101_COM dated 7/28/11"
  rect 0.36x0.32 smd mask+0.048: 1(-0.28,0) 2(0.28,0)
  body extent -0.31,-0.16 0.31,0.16, height 0.26
0402L#1 [mm] "0402 from SM-752 data"
  rect 0.6x0.5 smd: 1(-0.5,0) 2(0.5,0)
  body extent -0.55,-0.3 0.55,0.3, height 0.6
0402L#2 [mm] "0402 from SM-752 data"
  rrect20% 0.6x0.5 smd mask+0.051: 1(-0.5,0) 2(0.5,0)
  body extent -0.5,-0.25 0.5,0.25, height 0.35
0402L_cap#1 [mm] "0402 from SM-752 data"
  rect 0.6x0.5 smd: 1(-0.5,0) 2(0.5,0)
  body extent -0.55,-0.3 0.55,0.3, height 0.6
0402L_cap#2 [mm] "0402 from SM-752 data"
  rrect20% 0.6x0.5 smd mask+0.051: 1(-0.5,0) 2(0.5,0)
  body extent -0.55,-0.3 0.55,0.3, height 0.6
0603L [mm] "0603 from SM-752 data"
  rect 0.8x0.85 smd: 1(-0.7,0) 2(0.7,0)
  silkscreen extent -0.07,-0.33 0.07,0.33, body extent -0.87,-0.47 0.87,0.47, height 1
0603L_cap [mm] "0603 from SM-752 data"
  rect 0.8x0.85 smd: 1(-0.7,0) 2(0.7,0)
  silkscreen extent -0.07,-0.32 0.07,0.32, body extent -0.87,-0.47 0.87,0.47, height 1
0805L#1 [mm] "0805 from SM-752 data"
  rect 1.1x1.4 smd: 1(-0.75,0) 2(0.75,0)
  body extent -1.1,-0.72 1.1,0.72, height 1.45
0805L#2 [mm] "0805 from SM-752 data"
  rrect20% 1.1x1.4 smd: 1(-0.75,0) 2(0.75,0)
  body extent -1,-0.62 1,0.63, height 0.7
0805L_cap#1 [mm] "0805 from SM-752 data"
  rect 1.1x1.4 smd: 1(-0.75,0) 2(0.75,0)
  body extent -1.1,-0.72 1.1,0.72, height 1.45
0805L_cap#2 [mm] "0805 from SM-752 data"
  rrect20% 1.1x1.4 smd: 1(-0.75,0) 2(0.75,0)
  body extent -1.1,-0.72 1.1,0.72, height 1.45
1210L_cap [mm] "1210 from SM-752 data"
  rect 1.1x2.6 smd: 1(-1.35,0) 2(1.35,0)
  silkscreen extent -0.4,-1.2 0.4,1.2, body extent -1.7,-1.35 1.7,1.35, height 1.35
43045-1602 [mm]
  rect 1.52x1.52 / inner round 1.52 / far side rect 1.52x1.52 hole 1.02 mask+0.076: 1(0,0)
  round 1.52 hole 1.02 mask+0.076: 2(0,3) 3(-3,0) 4(-3,3) 5(-6,0) 6(-6,3) 7(-9,0) 8(-9,3) 9(-12,0) 10(-12,3) 11(-15,0) 12(-15,3) 13(-18,0) 14(-18,3) 15(-21,0) 16(-21,3)
  round 3 hole 3 unplated mask+0.076: ""(-18.85,-4.32) ""(-2.15,-4.32)
  silkscreen extent 3.75,-0.1 3.95,0.1, body extent -24.58,-8.92 3.57,3.32, height 8.73
434123050816 [mm] "SWITCH TACTILE SPST-NO 0.05A 12V"
  rrect10% 2x1.5 smd mask+0.05: 1(-2.7,0) 2(2.7,0)
  body extent -2.7,-1.47 2.7,1.47, height 3.23
450301014042 [mm]
  round 1.65 hole 1.016: 1(0,0) 2(-2.54,0)
  rect 1.65x1.65 hole 1.016: 3(2.54,0)
  silkscreen extent -4.25,-1.3 4.25,1.6, body extent -4.98,-1.25 5.02,1.25, height 5.9
ANH0289A [mm] "RF7x BGA package"
  round 0.45 smd paste+0 mask+0: A1(-6.4,6.4) A2(-5.6,6.4) A3(-4.8,6.4) A4(-4,6.4) A5(-3.2,6.4) A6(-2.4,6.4) A7(-1.6,6.4) A8(-0.8,6.4) A9(0,6.4) A10(0.8,6.4) A11(1.6,6.4) A12(2.4,6.4) A13(3.2,6.4) A14(4,6.4) A15(4.8,6.4) A16(5.6,6.4) A17(6.4,6.4) B1(-6.4,5.6) B2(-5.6,5.6) B3(-4.8,5.6) B4(-4,5.6) B5(-3.2,5.6) B6(-2.4,5.6) B7(-1.6,5.6) B8(-0.8,5.6) B9(0,5.6) B10(0.8,5.6) B11(1.6,5.6) B12(2.4,5.6) B13(3.2,5.6) B14(4,5.6) B15(4.8,5.6) B16(5.6,5.6) B17(6.4,5.6) C1(-6.4,4.8) C2(-5.6,4.8) C3(-4.8,4.8) C4(-4,4.8) C5(-3.2,4.8) C6(-2.4,4.8) C7(-1.6,4.8) C8(-0.8,4.8) C9(0,4.8) C10(0.8,4.8) C11(1.6,4.8) C12(2.4,4.8) C13(3.2,4.8) C14(4,4.8) C15(4.8,4.8) C16(5.6,4.8) C17(6.4,4.8) D1(-6.4,4) D2(-5.6,4) D3(-4.8,4) D4(-4,4) D5(-3.2,4) D6(-2.4,4) D7(-1.6,4) D8(-0.8,4) D9(0,4) D10(0.8,4) D11(1.6,4) D12(2.4,4) D13(3.2,4) D14(4,4) D15(4.8,4) D16(5.6,4) D17(6.4,4) E1(-6.4,3.2) E2(-5.6,3.2) E3(-4.8,3.2) E4(-4,3.2) E5(-3.2,3.2) E6(-2.4,3.2) E7(-1.6,3.2) E8(-0.8,3.2) E9(0,3.2) E10(0.8,3.2) E11(1.6,3.2) E12(2.4,3.2) E13(3.2,3.2) E14(4,3.2) E15(4.8,3.2) E16(5.6,3.2) E17(6.4,3.2) F1(-6.4,2.4) F2(-5.6,2.4) F3(-4.8,2.4) F4(-4,2.4) F5(-3.2,2.4) F6(-2.4,2.4) F7(-1.6,2.4) F8(-0.8,2.4) F9(0,2.4) F10(0.8,2.4) F11(1.6,2.4) F12(2.4,2.4) F13(3.2,2.4) F14(4,2.4) F15(4.8,2.4) F16(5.6,2.4) F17(6.4,2.4) G1(-6.4,1.6) G2(-5.6,1.6) G3(-4.8,1.6) G4(-4,1.6) G5(-3.2,1.6) G6(-2.4,1.6) G7(-1.6,1.6) G8(-0.8,1.6) G9(0,1.6) G10(0.8,1.6) G11(1.6,1.6) G12(2.4,1.6) G13(3.2,1.6) G14(4,1.6) G15(4.8,1.6) G16(5.6,1.6) G17(6.4,1.6) H1(-6.4,0.8) H2(-5.6,0.8) H3(-4.8,0.8) H4(-4,0.8) H5(-3.2,0.8) H6(-2.4,0.8) H7(-1.6,0.8) H8(-0.8,0.8) H9(0,0.8) H10(0.8,0.8) H11(1.6,0.8) H12(2.4,0.8) H13(3.2,0.8) H14(4,0.8) H15(4.8,0.8) H16(5.6,0.8) H17(6.4,0.8) J1(-6.4,0) J2(-5.6,0) J3(-4.8,0) J4(-4,0) J5(-3.2,0) J6(-2.4,0) J7(-1.6,0) J8(-0.8,0) J9(0,0) J10(0.8,0) J11(1.6,0) J12(2.4,0) J13(3.2,0) J14(4,0) J15(4.8,0) J16(5.6,0) J17(6.4,0) K1(-6.4,-0.8) K2(-5.6,-0.8) K3(-4.8,-0.8) K4(-4,-0.8) K5(-3.2,-0.8) K6(-2.4,-0.8) K7(-1.6,-0.8) K8(-0.8,-0.8) K9(0,-0.8) K10(0.8,-0.8) K11(1.6,-0.8) K12(2.4,-0.8) K13(3.2,-0.8) K14(4,-0.8) K15(4.8,-0.8) K16(5.6,-0.8) K17(6.4,-0.8) L1(-6.4,-1.6) L2(-5.6,-1.6) L3(-4.8,-1.6) L4(-4,-1.6) L5(-3.2,-1.6) L6(-2.4,-1.6) L7(-1.6,-1.6) L8(-0.8,-1.6) L9(0,-1.6) L10(0.8,-1.6) L11(1.6,-1.6) L12(2.4,-1.6) L13(3.2,-1.6) L14(4,-1.6) L15(4.8,-1.6) L16(5.6,-1.6) L17(6.4,-1.6) M1(-6.4,-2.4) M2(-5.6,-2.4) M3(-4.8,-2.4) M4(-4,-2.4) M5(-3.2,-2.4) M6(-2.4,-2.4) M7(-1.6,-2.4) M8(-0.8,-2.4) M9(0,-2.4) M10(0.8,-2.4) M11(1.6,-2.4) M12(2.4,-2.4) M13(3.2,-2.4) M14(4,-2.4) M15(4.8,-2.4) M16(5.6,-2.4) M17(6.4,-2.4) N1(-6.4,-3.2) N2(-5.6,-3.2) N3(-4.8,-3.2) N4(-4,-3.2) N5(-3.2,-3.2) N6(-2.4,-3.2) N7(-1.6,-3.2) N8(-0.8,-3.2) N9(0,-3.2) N10(0.8,-3.2) N11(1.6,-3.2) N12(2.4,-3.2) N13(3.2,-3.2) N14(4,-3.2) N15(4.8,-3.2) N16(5.6,-3.2) N17(6.4,-3.2) P1(-6.4,-4) P2(-5.6,-4) P3(-4.8,-4) P4(-4,-4) P5(-3.2,-4) P6(-2.4,-4) P7(-1.6,-4) P8(-0.8,-4) P9(0,-4) P10(0.8,-4) P11(1.6,-4) P12(2.4,-4) P13(3.2,-4) P14(4,-4) P15(4.8,-4) P16(5.6,-4) P17(6.4,-4) R1(-6.4,-4.8) R2(-5.6,-4.8) R3(-4.8,-4.8) R4(-4,-4.8) R5(-3.2,-4.8) R6(-2.4,-4.8) R7(-1.6,-4.8) R8(-0.8,-4.8) R9(0,-4.8) R10(0.8,-4.8) R11(1.6,-4.8) R12(2.4,-4.8) R13(3.2,-4.8) R14(4,-4.8) R15(4.8,-4.8) R16(5.6,-4.8) R17(6.4,-4.8) T1(-6.4,-5.6) T2(-5.6,-5.6) T3(-4.8,-5.6) T4(-4,-5.6) T5(-3.2,-5.6) T6(-2.4,-5.6) T7(-1.6,-5.6) T8(-0.8,-5.6) T9(0,-5.6) T10(0.8,-5.6) T11(1.6,-5.6) T12(2.4,-5.6) T13(3.2,-5.6) T14(4,-5.6) T15(4.8,-5.6) T16(5.6,-5.6) T17(6.4,-5.6) U1(-6.4,-6.4) U2(-5.6,-6.4) U3(-4.8,-6.4) U4(-4,-6.4) U5(-3.2,-6.4) U6(-2.4,-6.4) U7(-1.6,-6.4) U8(-0.8,-6.4) U9(0,-6.4) U10(0.8,-6.4) U11(1.6,-6.4) U12(2.4,-6.4) U13(3.2,-6.4) U14(4,-6.4) U15(4.8,-6.4) U16(5.6,-6.4) U17(6.4,-6.4)
  silkscreen extent -7.74,-7 7,7, body extent -6.9,-6.9 6.9,6.9, height 1.4
AssemblyNote [mil] "Assembly Note"
AssemblyNoteLabel [mil] "Assembly Note for PCB Labels"
BQB0016A-MFG [mm]
  rrect42% 0.24x0.6 smd paste+0 mask+0.07: 1(-0.25,1.65) 8(-0.25,-1.65) 9(0.25,-1.65) 16(0.25,1.65)
  rrect42% 0.6x0.24 smd paste+0 mask+0.07: 2(-1.15,1.25) 3(-1.15,0.75) 4(-1.15,0.25) 5(-1.15,-0.25) 6(-1.15,-0.75) 7(-1.15,-1.25) 10(1.15,-1.25) 11(1.15,-0.75) 12(1.15,-0.25) 13(1.15,0.25) 14(1.15,0.75) 15(1.15,1.25)
  round 0.508 hole 0.254 mask+0.05: 17(0,-0.75) 17(0,0.75)
  rrect10% 1x2 smd paste-1000 mask+0.07: 17(0,0)
  silkscreen extent -1.67,-1.8 1.3,1.8, body extent -1.25,-1.75 1.25,1.75, height 0.8
CCS0603FLxLxx [mm] "1206 from SM-752 data"
  rrect33% 1.41x0.92 smd: 1(-0.9,0) 2(0.89,0)
  body extent -0.93,-0.52 0.93,0.52, height 0.66
CE_Mark_5mm [mil] "Minimum text height for CE Mark"
  silkscreen extent -138,-98 138,98
"DAC39 - ATS-54170R-C1-R0_BGA_HEATSINK_17p0x17p0mm" [mil]
  body extent -335,-335 335,335, height 860
"DAC39R - F17HA-05HC_FAN_17p0x17p0mm" [mil]
  body extent 0,-335 323,335, height 1004
"DB1627 - Vias 1,2,5" [mm]
  rrect10% 0.76x1.65 smd: 1(-1.27,1.59) 2(0,1.59) 3(1.27,1.59) 4(1.27,-1.59) 5(0,-1.59) 6(-1.27,-1.59)
  round 0.635 hole 0.381 mask+0.05: 5(-2.54,0) 5(-1.27,0) 5(-1.27,2.87) 5(-1.27,4.242) 5(0,0) 5(0,-2.87) 5(0,2.87) 5(0,4.242) 5(1.27,0)
  silkscreen extent -1.91,-1.91 1.91,3.09, body extent -1.91,-1.91 1.9,1.9, height 3.13
DBV0005A [mm] "SOT23, 5-Leads, Body 2.9x1.6mm, Pitch 0.95mm, Lead Span 2.8mm, IPC High Density"
  rrect18% 1.1x0.6 smd mask+0.07: 1(-1.3,0.95) 2(-1.3,0) 3(-1.3,-0.95) 4(1.3,-0.95) 5(1.3,0.95)
  silkscreen extent -0.35,-1.55 0.35,1.55, body extent -1.42,-1.46 1.42,1.46, height 1.09
DBV0006A [mm] "SOT23, 6-Leads, Body 2.9x1.6mm, Pitch 0.95mm, Lead Span 2.8mm, IPC High Density"
  rrect18% 1.1x0.6 smd mask+0.07: 1(-1.3,0.95) 2(-1.3,0) 3(-1.3,-0.95) 4(1.3,-0.95) 5(1.3,0) 6(1.3,0.95)
  silkscreen extent -0.35,-1.55 0.35,1.55, body extent -1.5,-1.5 1.5,1.5, height 1.3
DCK0005A [mm] "SOT353, 5-Leads, Body 2x1.3mm, Pitch 0.65mm, Lead Span 2.1mm, IPC High Density"
  rrect25% 0.9x0.4 smd mask+0.05: 1(-1.1,0.65) 2(-1.1,0) 3(-1.1,-0.65) 4(1.1,-0.65) 5(1.1,0.65)
  silkscreen extent -0.25,-1.1 0.25,1.1, body extent -1.14,-1 1.14,1, height 0.95
DCK0006A [mm] "SOT23, 6-Leads, Body 2x1.3mm, Pitch 0.65mm, Lead Span 2.1mm, IPC High Density"
  rrect25% 0.9x0.4 smd mask+0.05: 1(-1.1,0.65) 2(-1.1,0) 3(-1.1,-0.65) 4(1.1,-0.65) 5(1.1,0) 6(1.1,0.65)
  silkscreen extent -1.3,-1.07 0.55,1.1, body extent -1.14,-1 1.14,1, height 0.95
DCU0008A [mm] "TSSOP, 8-Leads, Body 2x2.3mm, Pitch 0.5mm, IPC High Density"
  rrect30% 0.8x0.3 smd mask+0.05: 1(-1.55,0.75) 2(-1.55,0.25) 3(-1.55,-0.25) 4(-1.55,-0.75) 5(1.55,-0.75) 6(1.55,-0.25) 7(1.55,0.25) 8(1.55,0.75)
  silkscreen extent -1.05,-1.05 0.38,1.05, body extent -1.56,-1 1.56,1, height 0.9
DQA0010A [mm] "SON, 10-Leads, Body 1x2.5mm, Pitch 0.5mm, TI Recommended"
  rrect50% 0.565x0.2 smd mask+0.07: 1(-0.417,1) 2(-0.417,0.5) 4(-0.418,-0.5) 5(-0.418,-1) 6(0.417,-1) 7(0.417,-0.5) 9(0.417,0.5) 10(0.417,1)
  rrect28% 0.565x0.36 on Top Paste mask+0.07: 3(-0.418,0) 8(0.417,0)
  rrect25% 0.565x0.4 smd paste-0.2 mask+0.07: 3(-0.417,0) 8(0.417,0)
  silkscreen extent -0.67,-1.45 0.55,1.45, body extent -0.5,-1.25 0.5,1.25, height 0.55
DQE0008A [mm] "SON, 8-Leads, Body 1.4x1mm, Pitch 0.35mm, TI Recommended"
  rrect20% 0.6x0.175 smd mask+0.05: 1(-0.4,0.525)
  rrect20% 0.5x0.175 smd mask+0.05: 2(-0.45,0.175) 3(-0.45,-0.175) 4(-0.45,-0.525) 5(0.45,-0.525) 6(0.45,-0.175) 7(0.45,0.175) 8(0.45,0.525)
  silkscreen extent -0.7,-0.85 0.4,0.85, body extent -0.5,-0.7 0.5,0.7, height 0.37
DQK0006C [mm] "WSON"
  rrect12% 0.9x0.86 on Bottom Paste: 0(0,0.325)
  rrect34% 0.7x0.29 on Bottom Paste: 0(0.095,-0.65)
  rrect33% 0.45x0.3 smd: 1(-0.975,0.65) 2(-0.975,0) 3(-0.975,-0.65) 4(0.975,-0.65) 5(0.975,0) 6(0.975,0.65)
  rrect33% 0.75x0.3 smd paste-0.15: 7(0.095,-0.65)
  rrect11% 1x0.95 smd paste-0.5: 8(0,0.325)
  silkscreen extent -1.15,-1.15 1.15,1.15, body extent -1,-1 1,1, height 0.75
DRC0010J [mm] "VSON-10"
  rrect42% 0.6x0.24 smd mask+0.07: 1(-1.4,1) 2(-1.4,0.5) 3(-1.4,0) 4(-1.4,-0.5) 5(-1.4,-1) 6(1.4,-1) 7(1.4,-0.5) 8(1.4,0) 9(1.4,0.5) 10(1.4,1)
  round 0.508 hole 0.254 mask+0.05: 11(-0.575,0) 11(0,-0.95) 11(0,0.95) 11(0.575,0)
  round 0.025 smd mask+0.07: 11(0,0)
  Top Layer region: -0.375,-1.65 -0.375,-1.2 -0.775,-1.2 -0.794,-1.196 -0.81,-1.185 -0.821,-1.169 -0.825,-1.15 -0.825,-1.15 -0.825,1.15 -0.821,1.169 -0.81,1.185 -0.794,1.196 -0.775,1.2 -0.775,1.2 -0.375,1.2 -0.375,1.65 -0.371,1.669 -0.36,1.685 -0.344,1.696 -0.325,1.7 -0.325,1.7 -0.325,1.7 -0.175,1.7 -0.175,1.7 -0.156,1.696 -0.14,1.685 -0.129,1.669 -0.125,1.65 -0.125,1.65 -0.125,1.2 0.125,1.2 0.125,1.65 0.129,1.669 0.14,1.685 0.156,1.696 0.175,1.7 0.175,1.7 0.175,1.7 0.325,1.7 0.325,1.7 0.344,1.696 0.36,1.685 0.371,1.669 0.375,1.65 0.375,1.65 0.375,1.2 0.775,1.2 0.794,1.196 0.81,1.185 0.821,1.169 0.825,1.15 0.825,1.15 0.825,-1.15 0.821,-1.169 0.81,-1.185 0.794,-1.196 0.775,-1.2 0.775,-1.2 0.375,-1.2 0.375,-1.65 0.371,-1.669 0.36,-1.685 0.344,-1.696 0.325,-1.7 0.325,-1.7 0.175,-1.7 0.156,-1.696 0.14,-1.685 0.129,-1.669 0.125,-1.65 0.125,-1.65 0.125,-1.2 -0.125,-1.2 -0.125,-1.65 -0.129,-1.669 -0.14,-1.685 -0.156,-1.696 -0.175,-1.7 -0.175,-1.7 -0.325,-1.7 -0.344,-1.696 -0.36,-1.685 -0.371,-1.669 -0.375,-1.65
  silkscreen extent -1.97,0.95 -1.84,1.08, body extent -1.5,-1.5 1.5,1.5, height 1
DRY0006A [mm]
  rrect20% 0.35x0.2 smd mask+0.05: 1(-0.298,0.5)
  rrect20% 0.3x0.2 smd mask+0.05: 2(-0.303,0) 3(-0.303,-0.5) 4(0.303,-0.5) 5(0.303,0) 6(0.303,0.5)
  silkscreen extent -0.5,0.74 -0.45,0.79, body extent -0.5,-0.72 0.5,0.72, height 0.6
ESD_Overlay_Small [mil]
  silkscreen extent -62,-48 64,61
FCC_disclaimer [mil]
FDL_Small [mil]
  silkscreen extent -54,-32 54,73
Fiducial10-20 [mm]
  round 1 smd paste-0.508 mask+0.203: 1(0,0)
FIL_BNX002-11 [mm]
  rect 1.8x1.8 hole 1.2: 1(2.5,2.5)
  round 1.8 hole 1.2: 2(2.5,-2.5) 3(-2.5,2.5) 4(-2.5,-2.5) 4(0,0) 4(5,0)
  silkscreen extent -6,-5.5 6,6.35, body extent -6,-5.5 6,5.5, height 13
FP-2116-440-AL_STANDOFF_HEX_1-4-MFG [mm]
  round 3.2 hole 3.2 unplated paste-2539.97 mask+0: ""(0,0)
  body extent -3.66,-3.17 3.66,3.18, height 31.88
FP-132134-15_CONN_SMA_JACK-MFG [mm]
  round 0.864 smd paste+0 mask+0: 1(0,0)
  round 2.6 hole 1.7 paste-2539.97 mask+0: 2(-2.54,2.54) 3(2.54,2.54) 4(-2.54,-2.54) 5(2.54,-2.54)
  silkscreen extent -3.6,-3.6 3.6,3.6, body extent -3.94,-3.94 3.94,3.94, height 0.25
FTDI_Dongle_003 [mm]
  rect 2.27x0.279 smd: 1(18.74,-7.25) 2(13.01,-7.25) 3(18.74,-6.75) 4(13.01,-6.75) 5(18.74,-6.25) 6(13.01,-6.25) 7(18.74,-5.75) 8(13.01,-5.75) 9(18.74,-5.25) 10(13.01,-5.25) 11(18.74,-4.75) 12(13.01,-4.75) 13(18.74,-4.25) 14(13.01,-4.25) 15(18.74,-3.75) 16(13.01,-3.75) 17(18.74,-3.25) 18(13.01,-3.25) 19(18.74,-2.75) 20(13.01,-2.75) 21(18.74,-2.25) 22(13.01,-2.25) 23(18.74,-1.75) 24(13.01,-1.75) 25(18.74,-1.25) 26(13.01,-1.25) 27(18.74,-0.75) 28(13.01,-0.75) 29(18.74,-0.25) 30(13.01,-0.25) 31(18.74,0.25) 32(13.01,0.25) 33(18.74,0.75) 34(13.01,0.75) 35(18.74,1.25) 36(13.01,1.25) 37(18.74,1.75) 38(13.01,1.75) 39(18.74,2.25) 40(13.01,2.25) 41(18.74,2.75) 42(13.01,2.75) 43(18.74,3.25) 44(13.01,3.25) 45(18.74,3.75) 46(13.01,3.75) 47(18.74,4.25) 48(13.01,4.25) 49(18.74,4.75) 50(13.01,4.75) 51(18.74,5.25) 52(13.01,5.25) 53(18.74,5.75) 54(13.01,5.75) 55(18.74,6.25) 56(13.01,6.25) 57(18.74,6.75) 58(13.01,6.75) 59(18.74,7.25) 60(13.01,7.25)
  round 2 hole 2.45 unplated: 4(-19.685,-10.16) 4(-19.685,10.16)
  round 0 hole 1.02 unplated: MH1(13.205,-10.065) MH2(13.205,10.065)
  rect 0.43x2.54 smd: MP1(15.875,-8.065) MP4(15.875,8.065)
  rect 0.43x4.7 smd: MP2(15.875,-3.175) MP3(15.875,3.175)
  silkscreen extent 12.26,-10.66 19.78,10.65, body extent -22.22,-12.7 22.23,13.2, height 10.54
HDR_5x1_TH_VT_50mil [mm] "TH, Header, 1.27 mm, 5x1, Straight"
  rect 1.05x1.05 hole 0.75: 1(-1.905,0)
  round 1.05 hole 0.75: 2(-0.635,0) 3(0.635,0) 4(1.905,0) 5(3.175,0)
  silkscreen extent -2.79,-1.07 4.06,1.35, body extent -2.79,-1.07 4.06,1.07, height 4.3
HDR_8x2_TH_VT_50mil [mm] "TH, Header, 1.27 mm, 8X2, Straight"
  rect 1.05x1.05 hole 0.75: 1(-4.445,0.635)
  round 1.05 hole 0.75: 2(-4.445,-0.635) 3(-3.175,0.635) 4(-3.175,-0.635) 5(-1.905,0.635) 6(-1.905,-0.635) 7(-0.635,0.635) 8(-0.635,-0.635) 9(0.635,0.635) 10(0.635,-0.635) 11(1.905,0.635) 12(1.905,-0.635) 13(3.175,0.635) 14(3.175,-0.635) 15(4.445,0.635) 16(4.445,-0.635)
  silkscreen extent -5.33,-1.71 5.33,1.98, body extent -5.33,-1.71 5.33,1.71, height 4.3
IEC_HotSurface_Small [mil]
  silkscreen extent -107,-93 107,92
Keystone5001 [mil] "For Keystone 500x miniature loop terminals"
  round 80 hole 40: 1(0,0)
  silkscreen extent -52,-52 52,52, body extent -49,-49 49,49, height 182
Keystone5002 [mil] "For Keystone 500x miniature loop terminals"
  round 80 hole 40: 1(0,0)
  silkscreen extent -52,-53 52,52, body extent -49,-49 49,49, height 182
Keystone5003 [mil] "For Keystone 500x miniature loop terminals"
  round 80 hole 40: 1(0,0)
  silkscreen extent -52,-52 52,52, body extent -49,-49 49,49, height 182
Keystone5010 [mil] "Keystone Multipurpose loops"
  round 87 hole 63: 1(0,0)
  silkscreen extent -70,-70 70,70, body extent -63,-63 63,62, height 319
Keystone5125 [mil] "Keystone Multipurpose loops"
  round 87 hole 63: 1(0,0)
  silkscreen extent -70,-70 70,70, body extent -63,-63 63,62, height 319
l-header [mm]
  rect 1.65x1.65 hole 1.016: 1(0,0)
  round 1.65 hole 1.016: 2(-2.54,0) 3(0,-2.54)
  silkscreen extent -3.81,-3.81 1.27,1.27, body extent -4,-3.81 1.27,1.27, height 8.38
Label_650x200 [mil] "Thermal Transfer Label"
  silkscreen extent -325,-100 325,100
LED_LTST-C190-Green [mm] "Lite-On"
  rect 0.8x0.8 smd: 1(-0.75,0) 2(0.75,0)
  silkscreen extent -1.1,-0.8 1.8,0.8, body extent -0.85,-0.45 0.85,0.45, height 0.91
Marki_BAL-000xSMG [mil] "SMD, 3-Leads, Body 320x320mil"
  round 42 smd mask+2.76: 1(0,166) 2(60,-166) 3(-60,-166)
  round 41 hole 25 mask+0: 4(-135,135) 4(-135,-135) 4(-80,75) 4(-80,-75) 4(80,75) 4(80,-75) 4(135,135) 4(135,-135)
  round 20 hole 10 mask+0: 4(-109,-150) 4(-91,-124) 4(-60,-114) 4(-49,150) 4(-49,90) 4(-31,124) 4(-31,90) 4(-29,-81) 4(-29,-124) 4(-11,-150) 4(0,114) 4(11,-150) 4(29,-81) 4(29,-124) 4(31,124) 4(31,90) 4(49,150) 4(49,90) 4(60,-114) 4(91,-124) 4(109,-150)
  round 1 smd mask+1.97: 4(0,0)
  Top Layer region: -165,-165.38 -100.42,-165.38 -94.98,-145.09 -80.12,-130.23 -59.83,-124.79 -59.83,-124.79 -44.3,-127.88 -31.13,-136.68 -22.33,-149.85 -19.24,-165.38 -19.24,-165.38 19.24,-165.38 24.68,-145.09 39.54,-130.23 59.83,-124.79 59.83,-124.79 75.36,-127.88 88.53,-136.68 97.33,-149.85 100.42,-165.38 100.42,-165.38 165,-165.38 165,165.38 40.46,165.38 37.38,149.85 28.58,136.68 15.41,127.88 -0.12,124.79 -0.12,124.79 -15.66,127.88 -28.82,136.68 -37.62,149.85 -40.71,165.38 -40.71,165.38 -165,165.38
  body extent -160,-160 160,160, height 155
Molex_0853050232 [mm] "Plug, 50 Ohm, Straight, SMT"
  rrect17% 0.6x1.3 smd: 1(0,0)
  round 0.654 hole 0.4 mask+0.05: 2(-2.3,-2.15) 2(-2.3,-3.95) 2(-1.4,-0.85) 2(-1.4,-5.25) 2(1.4,-0.85) 2(1.4,-5.25) 2(2.3,-2.15) 2(2.3,-3.95)
  round 0.025 smd: 2(0,-5.35)
  Top Layer pour cut-out: -0.33,0.699 -0.33,-0.698 0.33,-0.698 0.33,0.699
  Top Layer pour cut-out: 0.998,-1.315 0.998,-0.45 -0.998,-0.45 -0.998,-1.321 -1.679,-1.973 -1.986,-2.865 -1.849,-3.798 -1.3,-4.565 -0.461,-4.995 0.482,-4.992 1.319,-4.557 1.864,-3.787 1.995,-2.854 1.683,-1.963 0.998,-1.315
  Top Layer region: -2.6,-5.65 -2.6,-0.45 -1,-0.45 -1,-1.318 -1.732,-2.05 -2,-3.05 -1.732,-4.05 -1,-4.782 0,-5.05 1,-4.782 1.732,-4.05 2,-3.05 1.732,-2.05 1,-1.318 1,-1.318 1,-0.45 2.6,-0.45 2.6,-5.65
  L2 GND pour cut-out: -0.33,0.699 -0.33,-0.698 0.33,-0.698 0.33,0.699
  L2 GND pour cut-out: 0.998,-1.315 0.998,-0.45 -0.998,-0.45 -0.998,-1.321 -1.679,-1.973 -1.986,-2.865 -1.849,-3.798 -1.3,-4.565 -0.461,-4.995 0.482,-4.992 1.319,-4.557 1.864,-3.787 1.995,-2.854 1.683,-1.963 0.998,-1.315
  L2 GND pour cut-out: 0.998,-1.315 0.998,-0.45 -0.998,-0.45 -0.998,-1.321 -1.679,-1.973 -1.986,-2.865 -1.849,-3.798 -1.3,-4.565 -0.461,-4.995 0.482,-4.992 1.319,-4.557 1.864,-3.787 1.995,-2.854 1.683,-1.963 0.998,-1.315
  L3 PWR pour cut-out: 0.998,-1.315 0.998,-0.45 -0.998,-0.45 -0.998,-1.321 -1.679,-1.973 -1.986,-2.865 -1.849,-3.798 -1.3,-4.565 -0.461,-4.995 0.482,-4.992 1.319,-4.557 1.864,-3.787 1.995,-2.854 1.683,-1.963 0.998,-1.315
  body extent -2.5,-5.55 2.5,0.45, height 4.1
Net-Tie_6x8mil [mil]
  rect 4x6 on Mid5 paste-5 mask-5: 1(-2,0) 2(2,0)
Net-Tie_50milWide_30milLong#1 [mil] "50mil net tie, no solder mask opening, no solder paste"
  rect 30x100 on Mid14 paste-20 mask-20: 1(-15,0) 2(15,0)
Net-Tie_50milWide_30milLong#2 [mil] "50mil net tie, no solder mask opening, no solder paste"
  rect 30x170 on Mid14 paste-20 mask-20: 1(-15,0) 2(15,0)
NFM31PC [mil]
  rrect10% 37.4x47.24 smd paste+0: 1(-65.94,0) 3(65.94,0)
  round 20 hole 10 mask+1.97: 2(-12,-43.5) 2(-12,43.5) 2(12,-43.5) 2(12,43.5)
  rrect10% 39.37x39.37 smd paste+0: 2(0,-31.5) 2(0,31.5)
  body extent -67,-36 67,36, height 59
